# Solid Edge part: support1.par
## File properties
Author: jmrobins
Template: sync iso part.par
Last saved by: mokuno
Revision: 21
Application: Solid Edge
Username: jmrobins
文書内容のタイプ: 0
Accuracy: 0.990
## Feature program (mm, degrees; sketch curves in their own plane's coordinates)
sketch for "unnamed Hole 1" plane through (0, -65, 130) normal (0, -1, 0) x-axis (1, 0, 0)
hole "unnamed Hole 1" through
pattern "unnamed Pattern 1" of "unnamed Hole 1"
sketch for "unnamed Hole 2" plane through (-2.1905, 3.4395, 0) normal (0, 0, 1) x-axis (0, 1, 0)
  hole centre (11.5605, 47.8095) bore radius 13
hole "unnamed Hole 2" through
sketch for "unnamed Hole 3" plane through (7.8909, 4.9229, 0) normal (0, 0, 1) x-axis (0, 1, 0)
  hole centre (10.0771, -42.1091) bore radius 13
hole "unnamed Hole 3" through
pattern "unnamed Pattern 2" of "unnamed Hole 3", "unnamed Hole 2"
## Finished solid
Body 1: solid body, 19 faces, 46 edges, 26 vertices.
  Faces by surface: plane 13, cylinder 6
  Edges by curve: line 33, circle 13
Bounding box of the edges (mm): 160.000 x 110.000 x 182.500, from (-80, -65, -20) to (80, 45, 162.5).
Cylindrical faces by radius (mm): R13 x2, R17.5 x1, R25 x2, R32.5 x1
Planar faces by outward normal: +x 3, +y 2, +z 1, -x 3, -y 2, -z 1, oblique 1
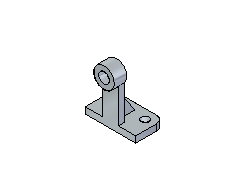
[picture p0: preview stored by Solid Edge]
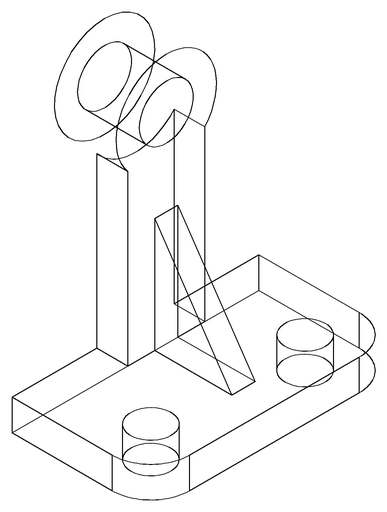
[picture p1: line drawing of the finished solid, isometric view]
